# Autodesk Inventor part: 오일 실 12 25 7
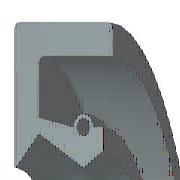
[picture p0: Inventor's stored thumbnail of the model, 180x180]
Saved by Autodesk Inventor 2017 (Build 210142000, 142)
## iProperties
IsCustomPart: 1
Created: 2012-02
Part Number: 오일 실 12 25 7
Material: 고무
Description: 오일-실
Document SubType Name: Modeling
Standard: KS B 2804
Designer: test
Standards Organization: KS
Language: ko-KR
Size Designation: D - 12 25 7
Categories: <MemberInstance><Categories><Category DisplayName="샤프트 부품" InternalName="7f7aeb1f-a693-4053-b835-cee3144e0d98" Mnemonic="SHFT"><Category DisplayName="실링" Intern
Density: 0.93 g/cm^3
Appearance: 고무 - 검은색 - 버전 1.1
Author: test
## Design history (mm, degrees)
revolve "본체" stored, may be unused: angle "d17" = 90 deg
revolve "스프링1" stored, may be unused: angle "d18" = 90 deg
body "Solid1"
sketch "스케치1"
  geometry: L1 (0, 12.5)-(7, 12.5); L2 (7, 10.75)-(1.75, 10.75); L3 (1.75, 7.75)-(4.9, 6); L4 (4.9, 6)-(0, 6); L5 (0, 0)-(9.586, 0) reference; L6 (4.9, 6)-(6.3, 6.875); L7 (0, 18)-(0, -3) reference; L8 (-1.941, 0)-(11.507, 0) reference; L9 (4.2, 8.1)-(1.75, 8.59); L10 (1.75, 8.59)-(1.75, 10.75); L11 (0, 12.5)-(0, 6.088); L12 (4.9, 6)-(0, 6); L13 (1.75, 7.75)-(0.152, 6.028); L14 (7, 12.5)-(7, 10.75); L15 (5.6, 8.1)-(6.3, 8.1); L16 (6.3, 8.1)-(6.3, 6.875); C1 r 0.455 at (4.9, 8.1); A1 r 0.7 centre (4.9, 8.1) between (5.6, 8.1) and (4.2, 8.1); A2 r 0.088 centre (0.088, 6.088) between (0, 6.088) and (0.152, 6.028); 1 further point
  constraints: 28 end point, 5 horizontal alignment, 5 point on line, 4 point on circle, 4 vertical alignment, 3 centre point, 3 tangent, 2 collinear, 2 horizontal, 2 perpendicular, 1 coincident, 1 parallel
  dimensions: "d0" = 25 diameter of L1 L5 (= SD2); "d1" = 1.75 distance of L1.end L2.start (= SD); "d2" = 0.91 diameter of C1 (= SPDI); "d3" = 1.4 diameter of A1 (= SPDA); "d4" = 12 diameter of L3.end L5 (= NND); "d5" = 15.5 diameter of L3.start L5 (= TKDM); "d7" = 17.18 diameter of L9.end L5 (= TKDM + 0.24 x SWDT); "d8" = 1.75 distance between parallel lines of L11 L10 (= SD); "d9" = 4.9 distance from line of L11 C1.centre (= SPDST); "d10" = 16.2 diameter of C1.centre L5 (= HLDM); "d11" = 0.0875 radius of A2 (= 0.25 x LAB); "d12" = 6.3 distance between parallel lines of L11 L16 (= SDI); "d13" = 13.75 diameter of L6.end L5 (= ABDM); "d14" = 7 distance from line of L11 L1.end (= SWDT)
fillet "모깎기1" dims "d6" = 0.3 (= RR)
other parameters: "SD2" = 25 [user parameter; used in 1 equation term], "SWDT" = 7 [user parameter; used in 2 equation terms], "RR" = 0.3 [user parameter; used in 1 equation term], "SD" = 1.75 [user parameter; used in 2 equation terms], "NND" = 12 [user parameter; used in 1 equation term], "SPDA" = 1.4 [user parameter; used in 1 equation term], "SPDI" = 0.91 [user parameter; used in 1 equation term], "TKDM" = 15.5 [user parameter; used in 2 equation terms], "HLDM" = 16.2 [user parameter; used in 1 equation term], "ABDM" = 13.75 [user parameter; used in 1 equation term], "SDI" = 6.3 [user parameter; used in 1 equation term], "SPDST" = 4.9 [user parameter; used in 1 equation term], "LAB" = 0.35 [user parameter; used in 1 equation term], "d15" = 0, "d16" = 0, "d19" = 0
